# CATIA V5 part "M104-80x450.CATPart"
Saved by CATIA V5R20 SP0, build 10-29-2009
Part number: M104-80x450
Source: Unknown
Bounding box of the stored display mesh (mm): x -39.842 to 39.842, y -39.842 to 39.842, z 0 to 450
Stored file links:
  C:\Users\Utente\Desktop\IO LAVORO\3D X SITO CF\X SITO\M104\M104-80x450.CATPart

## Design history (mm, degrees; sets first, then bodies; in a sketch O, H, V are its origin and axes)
Body1 (main body)
  Solid1 "PartBody": solid without history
